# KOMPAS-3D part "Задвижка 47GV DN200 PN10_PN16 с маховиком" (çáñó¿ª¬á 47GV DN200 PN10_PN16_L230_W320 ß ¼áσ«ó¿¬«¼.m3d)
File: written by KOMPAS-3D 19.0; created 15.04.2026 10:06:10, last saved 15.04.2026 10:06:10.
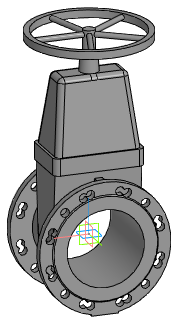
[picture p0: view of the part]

Document properties: Автор: Евгений; Полное имя файла: Z:\3.Личные\kachalov\3d для проектировщиков\2.1 Тип 47GV, 47GV.Z\Задвижка 47GV_DN40-DN600\stp_Задвижка 47GV\Задвижка 47GV DN200 PN10_PN16_L230_W320 с маховиком.m3d

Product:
- Part/product: Задвижка 47GV DN200 PN10_PN16 с маховиком

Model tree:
1. Операция без истории:1  (labels: Задвижка 47GV DN200 PN10_PN16 с маховиком)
